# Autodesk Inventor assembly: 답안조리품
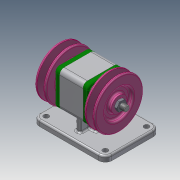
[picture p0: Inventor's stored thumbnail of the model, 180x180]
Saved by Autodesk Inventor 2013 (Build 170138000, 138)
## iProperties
Created: 2020-11
Part Number: 답안조리품
Document SubType Name: Assembly
Designer: user
Author: user
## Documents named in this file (10)
- C:\Users\user\Desktop\701106V1010\답안조립품.iam
- C:\Users\user\Desktop\701106V1010\본체.ipt
- C:\Users\user\Desktop\701106V1010\V-벨트풀리.ipt
- C:\Users\user\Desktop\701106V1010\너트 M10x1.ipt
- C:\Users\user\Desktop\701106V1010\베어링 6004.ipt
- C:\Users\user\Desktop\701106V1010\볼트 M4.ipt
- C:\Users\user\Desktop\701106V1010\오일 실 17 30 5.ipt
- C:\Users\user\Desktop\701106V1010\축.ipt
- C:\Users\user\Desktop\701106V1010\커버.ipt
- C:\Users\user\Desktop\701106V1010\키 5 x 5 x 12.ipt
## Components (2 placed, 1 different names)
1. V-벨트풀리:1
2. V-벨트풀리:2
